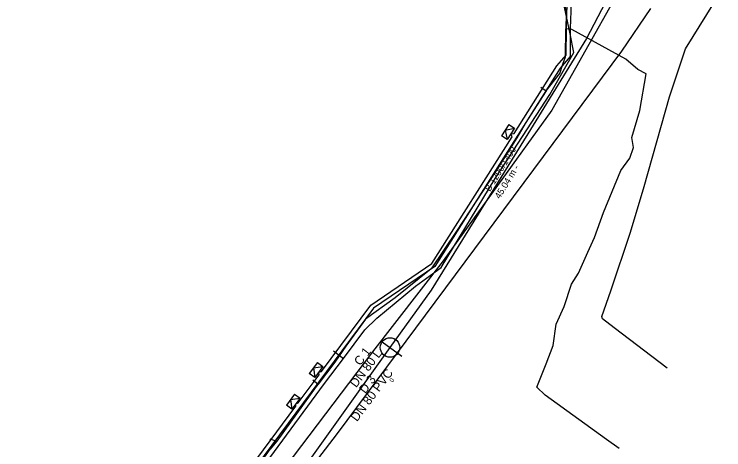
# Model space of a CAD drawing. Extents: x -600636 to -600148, y -1203980 to -1203569.
# Drawn here: x -600302.2 to -600229.4, y -1203773.6 to -1203728.9 of the extents above; entities that cross this region are included whole.
import ezdxf

# ---------------------------------------------------------------- set-up
doc = ezdxf.new("R2010")
doc.units = 0
for name, color, linetype in [('Cetin zam průběh', 7, 'Continuous'), ('EON podzemní NN', 7, 'Continuous'), ('GasNet NTL', 7, 'Continuous'), ('Implicitní', 7, 'Continuous'), ('VaK Břeclav_kanalizace', 7, 'Continuous'), ('Vak Břeclav_vodovod', 7, 'Continuous'), ('Vrstva 9', 7, 'Continuous')]:
    doc.layers.add(name, color=color, linetype=linetype)

# ---------------------------------------------------------------- blocks, each defined once
blk = doc.blocks.new('NN630')
at = {"layer": 'Vrstva 9'}
for points in [[(-0.003, -0.7), (-0.703, 0)], [(-0.703, -0.7), (-0.703, 0), (0.697, 0), (0.697, -0.7)], [(-0.703, -0.7), (0.697, -0.7)], [(-0.003, -0.7), (0.697, 0)]]:
    blk.add_lwpolyline(points, dxfattribs=at)
blk = doc.blocks.new('MoSymbol 2')
at = {"layer": 'Implicitní'}
blk.add_line((0, 0.0005), (0, -0.00075), dxfattribs=at)
blk.add_circle((0, 0), 0.0005, dxfattribs=at)

msp = doc.modelspace()

# ---------------------------------------------------------------- linework, layer by layer
at = {"layer": 'Cetin zam průběh'}
for points in [[(-600235.23, -1203765.23), (-600240.65, -1203761.08), (-600241.86, -1203760.15), (-600241.91, -1203759.91), (-600241.01, -1203757.3), (-600238.98, -1203751.29), (-600237.59, -1203746.58), (-600234.99, -1203737.4), (-600233.35, -1203732.5), (-600229.76, -1203726.69), (-600229.41, -1203725.62), (-600238.73, -1203718.32)], [(-600247.46, -1203726.17), (-600246.45, -1203726.91), (-600245.74, -1203727.75), (-600245.58, -1203728.9), (-600245.6, -1203730.45)], [(-600247.63, -1203736.78), (-600246.24, -1203735.03), (-600245.92, -1203734.07), (-600245.64, -1203733.29), (-600245.6, -1203730.45)], [(-600239.05, -1203743.7), (-600238.67, -1203742.61), (-600238.83, -1203741.58), (-600238.03, -1203738.79), (-600237.38, -1203735.06), (-600238.22, -1203734.62), (-600239.47, -1203733.54), (-600245.01, -1203730.52), (-600245.6, -1203730.45)], [(-600239.47, -1203733.54), (-600245.01, -1203730.52)], [(-600247.63, -1203736.78), (-600249.78, -1203740.13), (-600250.65, -1203741.61), (-600252.8, -1203745.02), (-600256.84, -1203751.19), (-600259.44, -1203755.05), (-600263.1, -1203758.01), (-600266.17, -1203760.2), (-600268.16, -1203762.96), (-600269.31, -1203764.61), (-600271.01, -1203766.87)], [(-600248.17, -1203736.43), (-600247.63, -1203736.78)], [(-600249.78, -1203740.13), (-600250.65, -1203741.61)], [(-600250.65, -1203741.61), (-600252.8, -1203745.02)], [(-600240.15, -1203773.44), (-600241.45, -1203772.54), (-600247.73, -1203767.99), (-600248.59, -1203767.15), (-600247.62, -1203764.78), (-600246.91, -1203762.88), (-600246.59, -1203760.7), (-600245.78, -1203758.89), (-600245.03, -1203756.62), (-600244.3, -1203755.49), (-600243.34, -1203753.33), (-600242.67, -1203751.82), (-600241.75, -1203749.25), (-600239.98, -1203744.96), (-600239.05, -1203743.7)], [(-600263.1, -1203758.01), (-600266.17, -1203760.2)], [(-600268.16, -1203762.96), (-600269.31, -1203764.61)], [(-600271.55, -1203766.42), (-600271.01, -1203766.87)], [(-600271.01, -1203766.87), (-600271.21, -1203767.09), (-600275.25, -1203772.7)], [(-600271.21, -1203767.09), (-600275.25, -1203772.7)], [(-600241.45, -1203772.54), (-600247.73, -1203767.99)], [(-600275.98, -1203772.47), (-600275.25, -1203772.7)], [(-600277, -1203775.03), (-600275.93, -1203773.51), (-600275.25, -1203772.7)], [(-600275.25, -1203772.7), (-600275.93, -1203773.51)]]:
    msp.add_lwpolyline(points, dxfattribs=at)
at = {"layer": 'EON podzemní NN'}
for points in [[(-600241.115, -1203718.296), (-600241.956, -1203719.116), (-600246.209, -1203724.801), (-600246.442, -1203725.59), (-600245.068, -1203727.725), (-600245.152, -1203730.414), (-600245.18, -1203733.274), (-600246.203, -1203734.474), (-600259.048, -1203754.786), (-600265.34, -1203759.062), (-600294.932, -1203798.94), (-600294.8, -1203799.42), (-600294.6, -1203799.71), (-600294.639, -1203800.117), (-600301.927, -1203809.794), (-600302.189, -1203809.81)], [(-600281.885, -1203780.687), (-600273.294, -1203769.109), (-600273.288, -1203768.864), (-600273.055, -1203768.788), (-600270.904, -1203765.889), (-600270.944, -1203765.611), (-600270.666, -1203765.567), (-600265.625, -1203758.774), (-600259.342, -1203754.503), (-600251.131, -1203741.518), (-600251.247, -1203741.205), (-600250.916, -1203741.179), (-600246.523, -1203734.232), (-600245.578, -1203733.124), (-600245.552, -1203730.406), (-600245.472, -1203727.837), (-600246.878, -1203725.652), (-600246.627, -1203724.801), (-600253.016, -1203720.855), (-600254.117, -1203722.507)]]:
    msp.add_lwpolyline(points, dxfattribs=at)
at = {"layer": 'GasNet NTL'}
for points in [[(-600295.95, -1203801.21), (-600295.65, -1203800.81), (-600287.36, -1203789.82), (-600286.53, -1203788.7), (-600278.7, -1203778.11), (-600278.55, -1203777.91), (-600275.98, -1203774.4), (-600270.38, -1203766.79), (-600268.42, -1203764.21), (-600266.21, -1203761.3), (-600264.99, -1203760.1), (-600261.02, -1203756.81), (-600258.4, -1203754.89), (-600252.86, -1203745.77), (-600247.26, -1203737.18), (-600244.78, -1203732.86), (-600245.17, -1203730.96), (-600245.99, -1203727.04), (-600245.48, -1203726.22)], [(-600269.45, -1203763.43), (-600268.42, -1203764.21)]]:
    msp.add_lwpolyline(points, dxfattribs=at)
at = {"layer": 'VaK Břeclav_kanalizace'}
for points in [[(-600240.031, -1203724.796), (-600243.482, -1203731.424), (-600245.022, -1203733.915), (-600249.522, -1203741.19), (-600259.43, -1203757.209), (-600263.646, -1203763.102)], [(-600263.646, -1203763.102), (-600288.953, -1203798.483), (-600301.999, -1203816.723)]]:
    msp.add_lwpolyline(points, dxfattribs=at)
at = {"layer": 'Vak Břeclav_vodovod'}
for points in [[(-600237.019, -1203720.962), (-600247.043, -1203738.764), (-600258.194, -1203754.202), (-600265.436, -1203763.558), (-600282.474, -1203785.988), (-600297.618, -1203805.864)], [(-600294.521, -1203805.29), (-600277.888, -1203783.466), (-600269.03, -1203771.912), (-600239.859, -1203732.742), (-600236.89, -1203728.365)]]:
    msp.add_lwpolyline(points, dxfattribs=at)

# ---------------------------------------------------------------- block references
at = {"layer": 'EON podzemní NN'}
for p, rotation in [((-600251.248, -1203741.205), -122.73661115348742), ((-600270.943, -1203765.611), -126.62638886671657), ((-600273.288, -1203768.864), -126.7565000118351)]:
    msp.add_blockref('NN630', p, dxfattribs=dict(at, rotation=rotation))
at = {"layer": 'VaK Břeclav_kanalizace', "xscale": 1999.750031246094, "yscale": 1999.750031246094, "rotation": 54.424444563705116}
msp.add_blockref('MoSymbol 2', (-600263.646, -1203763.102), dxfattribs=at)

# ---------------------------------------------------------------- texts
at = {"layer": 'VaK Břeclav_kanalizace'}
for s, height, rotation, p in [('- B 1200/1400', 0.68241, 58.26325, (-600253.687, -1203747.641)), ('45.04 m -', 0.6824, 58.26325, (-600252.389, -1203747.922)), ('0', 0.455, 54.42444, (-600263.383, -1203766.717))]:
    msp.add_text(s, height=height, rotation=rotation, dxfattribs=at).set_placement(p)
at = {"layer": 'Vak Břeclav_vodovod'}
for s, rotation, p in [('C 1', 52.77942, (-600266.69, -1203765.032)), ('DN 80 L', 52.77942, (-600267.119, -1203767.277)), ('DN 80 PVC', 53.32391, (-600267.033, -1203770.754)), ('D 3', 53.32391, (-600266.171, -1203767.897))]:
    msp.add_text(s, height=0.9099, rotation=rotation, dxfattribs=at).set_placement(p)

doc.saveas('drawing.dxf')
